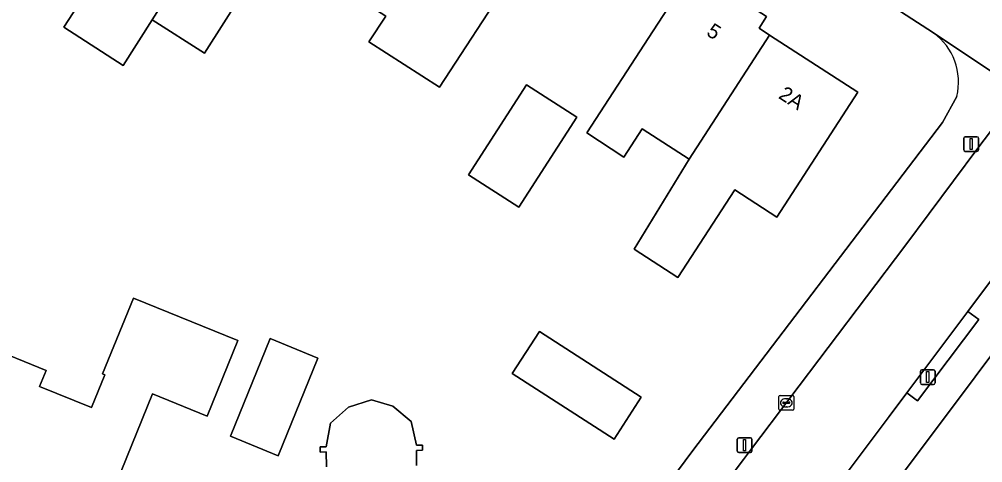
# Model space of a CAD drawing. Extents: x 161139 to 161601, y 381708 to 382245.
# Drawn here: x 161308.4 to 161373.8, y 381899.1 to 381929.2 of the extents above; entities that cross this region are included whole.
import ezdxf

# ---------------------------------------------------------------- set-up
doc = ezdxf.new("R2010")
doc.units = 0
for name, color, linetype in [('IMGEO_Erf', 7, 'Continuous'), ('IMGEO_Groenvoorziening', 7, 'Continuous'), ('IMGEO_Kolk', 7, 'Continuous'), ('IMGEO_Lichtmast', 7, 'Continuous'), ('IMGEO_Pand', 7, 'Continuous'), ('IMGEO_Pand_nummerreeks', 7, 'Continuous'), ('IMGEO_Rijbaan_lokaal_open', 7, 'Continuous'), ('IMGEO_Voetpad_open', 7, 'Continuous')]:
    doc.layers.add(name, color=color, linetype=linetype)

msp = doc.modelspace()

# ---------------------------------------------------------------- linework, layer by layer
at = {"layer": 'IMGEO_Erf'}
for points in [[(161370.462, 381928.258), (161276.309, 381989.126), (161276.14, 381989.025), (161267.873, 381937.797), (161267.435, 381933.784), (161267.467, 381929.855), (161267.871, 381925.589), (161268.634, 381921.624), (161269.796, 381917.444), (161271.533, 381912.948), (161272.783, 381910.378), (161277.045, 381903.774)], [(161326.262, 381935.133), (161321.004, 381926.887), (161317.459, 381929.147), (161315.487, 381926.054), (161311.476, 381928.656), (161317.797, 381938.4)], [(161371.073, 381922.177), (161372.043, 381923.95)], [(161342.481, 381884.773), (161344.76, 381887.264), (161354.145, 381899.917), (161371.073, 381922.177)], [(161329.29, 381898.8), (161329.269, 381899.821), (161328.851, 381899.813), (161328.845, 381900.163), (161329.256, 381900.171), (161329.556, 381901.782), (161330.778, 381902.87), (161332.33, 381903.365), (161333.779, 381902.935), (161335.03, 381901.876), (161335.401, 381900.28), (161335.8, 381900.286), (161335.805, 381899.936), (161335.385, 381899.929), (161335.401, 381898.908)]]:
    msp.add_lwpolyline(points, dxfattribs=at)
for points in [[(161326.534, 381933.789), (161330.165, 381939.387), (161332.886, 381943.581), (161333.193, 381943.382), (161333.975, 381944.588), (161341.086, 381939.976), (161340.269, 381938.717), (161344.399, 381936.038), (161341.679, 381931.844), (161336.953, 381924.571), (161332.168, 381927.644), (161333.306, 381929.397)], [(161351.442, 381928.397), (161354.162, 381932.591), (161359.145, 381929.359), (161358.634, 381928.571), (161359.346, 381928.109), (161365.323, 381924.232), (161359.827, 381915.759), (161356.981, 381917.605), (161353.123, 381911.657), (161350.154, 381913.584), (161353.883, 381919.687), (161350.705, 381921.748), (161349.464, 381919.835), (161346.947, 381921.467)], [(161342.846, 381924.74), (161346.258, 381922.545), (161342.328, 381916.436), (161338.915, 381918.631)], [(161316.193, 381910.265), (161323.278, 381907.381), (161321.194, 381902.259), (161317.489, 381903.766), (161313.947, 381895.06), (161312.062, 381890.428), (161305.111, 381893.257), (161305.8, 381894.95), (161305.424, 381895.103), (161305.852, 381896.154), (161306.302, 381895.986), (161306.706, 381897.067), (161302.753, 381898.676), (161306.145, 381907.012), (161310.258, 381905.339), (161309.82, 381904.264), (161313.34, 381902.832), (161314.245, 381905.055), (161314.097, 381905.115)], [(161325.457, 381907.509), (161328.699, 381906.19), (161326.005, 381899.566), (161322.762, 381900.886)], [(161343.735, 381908.005), (161350.642, 381903.53), (161348.795, 381900.679), (161341.888, 381905.154)]]:
    msp.add_lwpolyline(points, close=True, dxfattribs=at)
msp.add_arc((161368.047, 381924.928), 4.114, 346.25108, 54.05435, dxfattribs=at)
at = {"layer": 'IMGEO_Groenvoorziening'}
msp.add_lwpolyline([(161382.438, 381917.119), (161355.077, 381880.626)], dxfattribs=at)
at = {"layer": 'IMGEO_Kolk'}
for p, q in [((161359.98, 381902.729), (161359.98, 381903.581)), ((161360.055, 381903.655), (161360.907, 381903.655)), ((161360.981, 381903.581), (161360.981, 381902.729)), ((161360.239, 381903.149), (161360.239, 381903.161)), ((161360.677, 381903.112), (161360.279, 381903.112)), ((161360.282, 381903.198), (161360.68, 381903.198)), ((161360.491, 381902.875), (161360.466, 381902.875)), ((161360.468, 381903.435), (161360.493, 381903.435)), ((161360.723, 381903.161), (161360.723, 381903.149)), ((161360.907, 381902.655), (161360.055, 381902.655))]:
    msp.add_line(p, q, dxfattribs=at)
for points in [[(161359.98, 381902.729), (161359.98, 381903.581)], [(161360.055, 381903.655), (161360.907, 381903.655)], [(161360.981, 381903.581), (161360.981, 381902.729)], [(161360.907, 381902.655), (161360.055, 381902.655)]]:
    msp.add_lwpolyline(points, dxfattribs=at)
for centre, radius, start, end in [((161360.057, 381903.579), 0.0765, 91.55205, 178.44795), ((161360.057, 381903.579), 0.0765, 91.55205, 178.44795), ((161360.905, 381903.579), 0.0765, 1.55205, 88.44795), ((161360.905, 381903.579), 0.0765, 1.55205, 88.44795), ((161360.279, 381903.158), 0.0403, 85.87752, 175.75265), ((161360.276, 381903.148), 0.0366, 178.93798, 274.71019), ((161360.68, 381903.155), 0.043, 264.86636, 352.45326), ((161360.684, 381903.16), 0.0386, 1.73085, 96.63898), ((161360.057, 381902.731), 0.0765, 181.55205, 268.44795), ((161360.057, 381902.731), 0.0765, 181.55205, 268.44795), ((161360.905, 381902.731), 0.0765, 271.55205, 358.44795), ((161360.905, 381902.731), 0.0765, 271.55205, 358.44795)]:
    msp.add_arc(centre, radius, start, end, dxfattribs=at)
for centre, major_axis, ratio, start_param, end_param in [((161360.467, 381903.155), (-0.387, 0.002), 0.722429, 4.712389, 7.853982), ((161360.492, 381903.155), (-0.39, 0.002), 0.717154, 1.570796, 4.712389)]:
    msp.add_ellipse(centre, major_axis=major_axis, ratio=ratio, start_param=start_param, end_param=end_param, dxfattribs=at)
at = {"layer": 'IMGEO_Lichtmast'}
for p, q in [((161372.623, 381921.213), (161373.413, 381921.213)), ((161373.413, 381921.213), (161372.623, 381921.213)), ((161372.523, 381920.313), (161372.523, 381921.113)), ((161372.523, 381921.113), (161372.523, 381920.313)), ((161373.513, 381921.113), (161373.513, 381920.313)), ((161373.513, 381920.313), (161373.513, 381921.113)), ((161373.413, 381920.213), (161372.623, 381920.213)), ((161372.623, 381920.213), (161373.413, 381920.213)), ((161369.581, 381904.5), (161369.581, 381905.3)), ((161369.581, 381905.3), (161369.581, 381904.5)), ((161369.681, 381905.4), (161370.471, 381905.4)), ((161370.471, 381905.4), (161369.681, 381905.4)), ((161370.571, 381905.3), (161370.571, 381904.5)), ((161370.571, 381904.5), (161370.571, 381905.3)), ((161370.471, 381904.4), (161369.681, 381904.4)), ((161369.681, 381904.4), (161370.471, 381904.4)), ((161357.15, 381899.88), (161357.15, 381900.68)), ((161357.15, 381900.68), (161357.15, 381899.88)), ((161357.25, 381900.78), (161358.04, 381900.78)), ((161358.04, 381900.78), (161357.25, 381900.78)), ((161358.14, 381900.68), (161358.14, 381899.88)), ((161358.14, 381899.88), (161358.14, 381900.68)), ((161358.04, 381899.78), (161357.25, 381899.78)), ((161357.25, 381899.78), (161358.04, 381899.78))]:
    msp.add_line(p, q, dxfattribs=at)
for points in [[(161372.943, 381921.088), (161373.093, 381921.088), (161373.093, 381920.338), (161372.943, 381920.338), (161372.943, 381921.088)], [(161370.001, 381905.275), (161370.151, 381905.275), (161370.151, 381904.525), (161370.001, 381904.525), (161370.001, 381905.275)], [(161357.57, 381900.655), (161357.72, 381900.655), (161357.72, 381899.905), (161357.57, 381899.905), (161357.57, 381900.655)]]:
    msp.add_lwpolyline(points, dxfattribs=at)
for centre, start, end in [((161372.623, 381921.113), 90, 180), ((161372.623, 381921.113), 90, 180), ((161373.413, 381921.113), 0, 90), ((161373.413, 381921.113), 360, 90), ((161372.623, 381920.313), 180, 270), ((161372.623, 381920.313), 180, 270), ((161373.413, 381920.313), 270, 0), ((161373.413, 381920.313), 270, 0), ((161369.681, 381905.3), 90, 180), ((161369.681, 381905.3), 90, 180), ((161370.471, 381905.3), 0, 90), ((161370.471, 381905.3), 360, 90), ((161369.681, 381904.5), 180, 270), ((161369.681, 381904.5), 180, 270), ((161370.471, 381904.5), 270, 0), ((161370.471, 381904.5), 270, 0), ((161357.25, 381900.68), 90, 180), ((161357.25, 381900.68), 90, 180), ((161358.04, 381900.68), 0, 90), ((161358.04, 381900.68), 360, 90), ((161357.25, 381899.88), 180, 270), ((161357.25, 381899.88), 180, 270), ((161358.04, 381899.88), 270, 0), ((161358.04, 381899.88), 270, 0)]:
    msp.add_arc(centre, 0.1, start, end, dxfattribs=at)
at = {"layer": 'IMGEO_Pand'}
for points in [[(161319.778, 381941.251), (161323.542, 381947.053), (161322.283, 381947.869), (161324.177, 381950.789), (161322.208, 381952.066), (161322.611, 381952.686), (161319.625, 381954.622), (161319.229, 381954.011), (161317.942, 381954.845), (161312.965, 381947.06), (161316.394, 381944.835), (161313.857, 381940.924), (161316.587, 381939.175), (161317.797, 381938.4), (161311.476, 381928.656), (161315.487, 381926.054), (161317.459, 381929.147), (161323.208, 381938.163), (161323.465, 381938.504), (161323.627, 381938.754)], [(161341.679, 381931.844), (161344.399, 381936.038), (161340.269, 381938.717), (161341.086, 381939.976), (161333.975, 381944.588), (161333.193, 381943.382), (161332.886, 381943.581), (161330.165, 381939.387), (161326.534, 381933.789), (161333.306, 381929.397), (161332.168, 381927.644), (161336.953, 381924.571)], [(161326.262, 381935.133), (161326.953, 381936.241), (161323.465, 381938.504), (161323.208, 381938.163), (161317.459, 381929.147), (161321.004, 381926.887)], [(161353.883, 381919.687), (161359.346, 381928.109), (161358.634, 381928.571), (161359.145, 381929.359), (161354.162, 381932.591), (161351.442, 381928.397), (161346.947, 381921.467), (161349.464, 381919.835), (161350.705, 381921.748)], [(161353.883, 381919.687), (161350.154, 381913.584), (161353.123, 381911.657), (161356.981, 381917.605), (161359.827, 381915.759), (161365.323, 381924.232), (161359.346, 381928.109)], [(161342.328, 381916.436), (161346.258, 381922.545), (161342.846, 381924.74), (161338.915, 381918.631)], [(161312.062, 381890.428), (161313.947, 381895.06), (161317.489, 381903.766), (161321.194, 381902.259), (161323.278, 381907.381), (161316.193, 381910.265), (161314.097, 381905.115), (161314.245, 381905.055), (161313.34, 381902.832), (161309.82, 381904.264), (161310.258, 381905.339), (161306.145, 381907.012), (161302.753, 381898.676), (161306.706, 381897.067), (161306.302, 381895.986), (161305.852, 381896.154), (161305.424, 381895.103), (161305.8, 381894.95), (161305.111, 381893.257)], [(161326.005, 381899.566), (161328.699, 381906.19), (161325.457, 381907.509), (161322.762, 381900.886)], [(161348.795, 381900.679), (161350.642, 381903.53), (161343.735, 381908.005), (161341.888, 381905.154)]]:
    msp.add_lwpolyline(points, close=True, dxfattribs=at)
msp.add_lwpolyline([(161335.401, 381898.908), (161335.385, 381899.929), (161335.805, 381899.936), (161335.8, 381900.286), (161335.401, 381900.28), (161335.03, 381901.876), (161333.779, 381902.935), (161332.33, 381903.365), (161330.778, 381902.87), (161329.556, 381901.782), (161329.256, 381900.171), (161328.845, 381900.163), (161328.851, 381899.813), (161329.269, 381899.821), (161329.29, 381898.8)], dxfattribs=at)
at = {"layer": 'IMGEO_Rijbaan_lokaal_open'}
for points in [[(161375.72, 381923.419), (161374.759, 381922.138), (161373.481, 381920.434), (161368.51, 381913.776), (161358.116, 381900.025), (161357.581, 381899.312), (161355.178, 381896.112), (161351.589, 381891.33), (161347.78, 381886.211)], [(161352.722, 381882.533), (161364.546, 381898.333), (161367.452, 381902.216), (161368.658, 381903.827), (161372.8, 381909.362), (161380.355, 381919.457)]]:
    msp.add_lwpolyline(points, dxfattribs=at)
at = {"layer": 'IMGEO_Voetpad_open'}
for points in [[(161327.462, 381959.489), (161318.89, 381965.138), (161315.173, 381967.548), (161315.062, 381967.62), (161311.114, 381970.18), (161307.482, 381972.536), (161299.753, 381977.533), (161278.323, 381991.478), (161276.309, 381989.126), (161370.462, 381928.258), (161376.195, 381924.445)], [(161376.195, 381924.445), (161370.462, 381928.258)], [(161372.043, 381923.95), (161371.073, 381922.177), (161354.145, 381899.917), (161344.76, 381887.264), (161342.481, 381884.773)], [(161347.78, 381886.211), (161351.589, 381891.33), (161355.178, 381896.112), (161357.581, 381899.312), (161358.116, 381900.025), (161368.51, 381913.776), (161373.481, 381920.434), (161374.759, 381922.138), (161375.72, 381923.419)], [(161380.355, 381919.457), (161372.8, 381909.362), (161373.53, 381908.815), (161369.388, 381903.281), (161368.658, 381903.827), (161367.452, 381902.216), (161364.546, 381898.333), (161352.722, 381882.533)], [(161355.077, 381880.626), (161382.438, 381917.119)]]:
    msp.add_lwpolyline(points, dxfattribs=at)
msp.add_lwpolyline([(161372.8, 381909.362), (161368.658, 381903.827), (161369.388, 381903.281), (161373.53, 381908.815)], close=True, dxfattribs=at)
msp.add_arc((161368.047, 381924.928), 4.114, 346.25108, 54.05435, dxfattribs=at)

# ---------------------------------------------------------------- texts
at = {"layer": 'IMGEO_Pand_nummerreeks'}
for s, rotation, p in [('5', 327.03234, (161354.994, 381928.142)), ('2A', 327.46063, (161359.888, 381923.863))]:
    msp.add_text(s, height=1, rotation=rotation, dxfattribs=at).set_placement(p)

doc.saveas('drawing.dxf')
